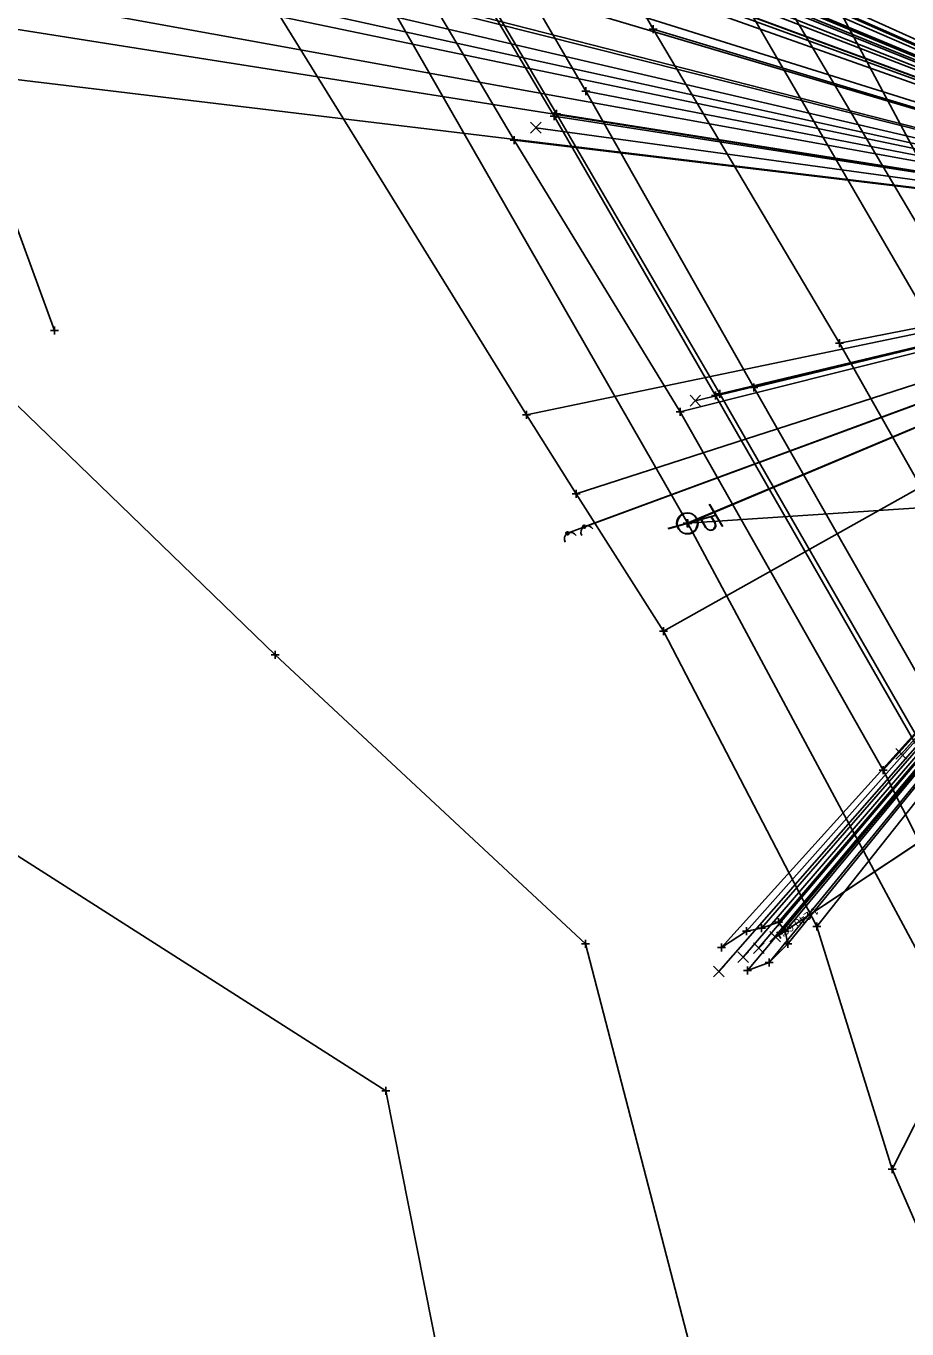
# Model space of a CAD drawing. Extents: x 125846 to 128609, y 511011 to 513388.
# Drawn here: x 126802 to 126912, y 512185.5 to 512348.3 of the extents above; entities that cross this region are included whole.
import ezdxf

# ---------------------------------------------------------------- set-up
doc = ezdxf.new("R2010")
doc.units = 0
for name, color, linetype in [('Default', 7, 'Continuous'), ('DR_X_Elev_Flow', 7, 'Continuous'), ('DR_X_Storm_Sewer', 7, 'Continuous'), ('DT_X_Terrain_Boundary', 7, 'Continuous'), ('PM_X_CL_Double_Solid', 7, 'Continuous'), ('PM_X_Edge_Line', 7, 'Continuous'), ('PV_X_COP', 7, 'Continuous'), ('PV_X_EOP', 7, 'Continuous'), ('PV_X_Shoulder_Aggregate', 7, 'Continuous'), ('SC_Scratch1', 7, 'Continuous'), ('SV_Observation', 7, 'Continuous'), ('SV_X_Break_Lines', 7, 'Continuous'), ('UT_X_Overhead_Cable_TV', 7, 'Continuous'), ('UT_X_Overhead_Electric', 7, 'Continuous'), ('UT_X_Overhead_Telecom', 7, 'Continuous'), ('UT_X_Sanitary_Line', 7, 'Continuous'), ('UT_X_Water', 7, 'Continuous')]:
    doc.layers.add(name, color=color, linetype=linetype)

msp = doc.modelspace()

# ---------------------------------------------------------------- linework, layer by layer
at = {"layer": 'Default'}
msp.add_lwpolyline([(126950.27, 512270.71), (126896.04, 512234.72)], dxfattribs=at)
at = {"layer": 'DR_X_Elev_Flow'}
for p, q in [((126895.78, 512235.15), (126896.29, 512234.29)), ((126896.47, 512234.98), (126895.61, 512234.46)), ((126896.04, 512234.72), (126896.04, 512234.72))]:
    msp.add_line(p, q, dxfattribs=at)
at = {"layer": 'DR_X_Storm_Sewer'}
msp.add_line((126950.27, 512270.71), (126896.04, 512234.72), dxfattribs=at)
at = {"layer": 'DT_X_Terrain_Boundary'}
for p, q in [((126888.13, 512287.21), (126882.16, 512285.53)), ((126888.21, 512287.19), (126882.24, 512285.5)), ((126888.95, 512285.84), (126887.32, 512288.59)), ((126889.03, 512285.81), (126887.4, 512288.56)), ((126886.27, 512286.69), (126886.87, 512285.66)), ((126886.35, 512286.66), (126886.96, 512285.63)), ((126887.54, 512287.04), (126887.97, 512286.31)), ((126887.62, 512287.02), (126888.05, 512286.29))]:
    msp.add_line(p, q, dxfattribs=at)
msp.add_lwpolyline([(125846.69, 513261.19), (125875.31, 513245.95), (126009.25, 513207.63), (126080.54, 513192), (126142.96, 513158.02), (126206.38, 513135.49), (126259.08, 513074.36), (126304.85, 512994.55), (126350.94, 512892.86), (126399.4, 512837.01), (126444.39, 512764.88), (126478.48, 512701.77), (126505.17, 512625.3), (126548.6, 512574.83), (126585.51, 512529.31), (126642.38, 512427.86), (126692.36, 512342.31), (126792.51, 512249.95), (126846.91, 512215.27), (126869.14, 512103.04), (126895.84, 512003)], dxfattribs=at)
for centre, radius in [((126884.55, 512286.2), 1.3), ((126884.63, 512286.17), 1.3), ((126871.68, 512285.77), 0.2), ((126869.6, 512284.94), 0.2)]:
    msp.add_circle(centre, radius, dxfattribs=at)
for centre, radius, start, end in [((126872.08, 512285.08), 0.8, 30.7503, 210.7503), ((126887.43, 512285.98), 0.638, 209.627, 31.8736), ((126887.51, 512285.95), 0.638, 209.627, 31.8736), ((126870.01, 512284.25), 0.8, 30.7503, 210.7503)]:
    msp.add_arc(centre, radius, start, end, dxfattribs=at)
at = {"layer": 'PM_X_CL_Double_Solid'}
msp.add_lwpolyline([(126939.36, 512245.71), (126926.53, 512268.2), (126903.61, 512308.72), (126880.31, 512347.95), (126860.08, 512383.78), (126836.45, 512422.71), (126813.37, 512462.31), (126785.22, 512508.84), (126764.44, 512544.16), (126739.79, 512584.78), (126713.11, 512629.69), (126694.8, 512659.53), (126673.4, 512694.56), (126659.78, 512718.87), (126636.02, 512759.4), (126615.05, 512794.2)], dxfattribs=at)
at = {"layer": 'PM_X_Edge_Line'}
for points in [[(126939.76, 512268.27), (126934.83, 512276.58), (126914.19, 512312.69), (126890.63, 512353.25), (126869.42, 512389.87), (126846.67, 512428.48), (126823.41, 512467.73), (126794.97, 512514.66), (126774.58, 512549.57), (126749.78, 512590.91), (126723.56, 512634.84), (126704.42, 512666.64), (126684.14, 512700.85), (126669.31, 512725.83), (126646.48, 512764.3), (126625.05, 512800.49)], [(127014.22, 511994.67), (127008.74, 512027.93), (127002.46, 512058.5), (126993.31, 512093.24), (126982.03, 512126.92), (126970.04, 512156.98), (126953.19, 512193.55), (126935.8, 512226.68), (126917.39, 512260.22), (126892.88, 512303.17), (126871.92, 512340.19), (126849.82, 512378.04), (126827.08, 512416.35), (126803.29, 512457.19), (126775.62, 512503), (126753.96, 512539.45), (126730.45, 512578.35), (126703.69, 512623.21), (126684.57, 512654.53), (126663.09, 512690.45), (126641.9, 512726.19), (126625.34, 512754.34)]]:
    msp.add_lwpolyline(points, dxfattribs=at)
at = {"layer": 'PV_X_COP'}
msp.add_lwpolyline([(127025.59, 511995.55), (127019.45, 512030.69), (127013.3, 512061.05), (127004.63, 512096.26), (126993.03, 512130.62), (126980.7, 512161.86), (126964.16, 512198.2), (126949.17, 512227.35), (126939.36, 512245.71), (126926.53, 512268.2), (126903.61, 512308.72), (126880.31, 512347.95), (126860.08, 512383.78), (126836.45, 512422.71), (126813.37, 512462.31), (126785.22, 512508.84), (126764.44, 512544.16), (126739.79, 512584.78), (126713.11, 512629.69), (126694.8, 512659.53), (126673.4, 512694.56), (126659.78, 512718.87), (126636.02, 512759.4), (126615.05, 512794.2)], dxfattribs=at)
at = {"layer": 'PV_X_EOP'}
for points in [[(127009.24, 511994.68), (127003.85, 512026.38), (126997.51, 512058.07), (126988.66, 512091.67), (126977.69, 512125.16), (126966.08, 512154.56), (126949.33, 512191.55), (126932.37, 512224.67), (126914.07, 512258.17), (126888.63, 512302.37), (126868.22, 512337.37), (126845.35, 512376.1), (126823.19, 512414), (126798.67, 512454.84), (126771.81, 512500.22), (126749.09, 512537.74), (126726.79, 512574.99), (126699.29, 512620.77), (126681.79, 512650.22), (126658.69, 512688.93), (126637.98, 512724.06), (126621.53, 512752.01)], [(127037.88, 512019.28), (127029.7, 512062.96), (127023.05, 512092.2), (127012.4, 512127.76), (127009.4, 512137.03), (126996.87, 512167.97), (126984.43, 512195.87), (126972.83, 512218.04), (126964.85, 512234.2), (126954.02, 512254.15), (126946.28, 512268.48), (126939.96, 512279.02), (126918.51, 512314.81), (126894.74, 512355.01), (126873.07, 512391.8), (126850.03, 512430.62), (126826.94, 512469.56), (126798.53, 512517.08)]]:
    msp.add_lwpolyline(points, dxfattribs=at)
at = {"layer": 'PV_X_Shoulder_Aggregate'}
for points in [[(126958.84, 512266.38), (126954.95, 512268.11), (126951.37, 512267.01), (126950.82, 512267.63), (126947.71, 512272.62), (126942.59, 512279.94), (126923.26, 512313.49), (126899.24, 512358.52), (126887.06, 512383.39), (126879.44, 512396.24), (126854.35, 512434.48), (126831.72, 512472.74), (126803.3, 512520.89), (126783.27, 512554.62), (126752.52, 512603.43), (126737.93, 512626.87), (126732.3, 512635.67), (126721.04, 512651.9), (126710.1, 512670.46), (126691.09, 512704.83), (126677.85, 512725.45), (126654.7, 512768.66), (126631.69, 512807.54)], [(127001.96, 511993.51), (126995.22, 512024.86), (126988.72, 512057.22), (126979.9, 512089.29), (126975.16, 512101.99), (126973.89, 512105.14), (126967.21, 512120.99), (126955.55, 512150.69), (126941.55, 512187.26), (126925.87, 512221.96), (126909.07, 512255.35), (126883.68, 512300.11), (126862.94, 512334.06), (126844.36, 512365.44), (126840.97, 512368.63), (126839.14, 512371.49), (126839.18, 512375.17), (126816.49, 512410.45), (126794.03, 512452.96), (126773.19, 512490.81), (126746.65, 512537.28)]]:
    msp.add_lwpolyline(points, dxfattribs=at)
at = {"layer": 'SV_Observation'}
for p in [(126786.23, 512400.45), (126727.19, 512397.15), (126814.49, 512385.66), (126821.17, 512376.04), (126839.18, 512375.17), (126844.97, 512375.96), (126845.35, 512376.1), (126841.19, 512374.83), (126842.48, 512372.4), (126839.14, 512371.49), (126843.76, 512370.56), (126840.97, 512368.63), (126844.36, 512365.44), (126846.94, 512365.74), (126848.4, 512357.16), (126808.82, 512354.73), (126824.97, 512354.9), (126836, 512354.88), (126837.31, 512355.05), (126894.74, 512355.01), (126790.68, 512353.63), (126890.63, 512353.25), (126774.58, 512352.09), (126832.62, 512351.28), (126738.1, 512349.2), (126880.31, 512347.95), (126880.31, 512347.95), (126871.92, 512340.19), (126867.94, 512337.07), (126868.22, 512337.37), (126865.67, 512335.64), (126862.94, 512334.06), (126864.5, 512299.73), (126869.6, 512284.94), (126870.71, 512289.89), (126871.68, 512285.77), (126881.61, 512272.71), (126883.68, 512300.11), (126884.55, 512286.2), (126884.55, 512286.2), (126884.55, 512286.2), (126884.55, 512286.2), (126884.63, 512286.17), (126884.63, 512286.17), (126884.63, 512286.17), (126884.63, 512286.17), (126885.58, 512301.52), (126888.12, 512302.18), (126888.53, 512230.17), (126888.63, 512302.37), (126888.85, 512233.17), (126891.56, 512231.95), (126891.96, 512235.2), (126892.09, 512230.28), (126892.88, 512303.17), (126893.5, 512233.1), (126893.86, 512235.58), (126894.82, 512231.3), (126895.56, 512234.53), (126895.99, 512236.32), (126896.04, 512234.72), (126896.8, 512235.22), (126897.13, 512233.65), (126900.78, 512235.79), (126903.61, 512308.72), (126903.61, 512308.72), (126909.07, 512255.35), (126910.2, 512205.45), (126911.33, 512257.38)]:
    msp.add_line(p, (126968.53, 512321.46), dxfattribs=at)
at = {"layer": 'SV_X_Break_Lines'}
for points in [[(126929.12, 511999.3), (126903.84, 512110.39), (126871.86, 512233.61), (126833.09, 512269.75), (126730.01, 512369.5), (126679.2, 512443.95), (126610.71, 512557), (126575.33, 512586.13), (126534.96, 512653.66), (126509.99, 512711.61), (126473.57, 512790.72), (126439.57, 512852.97), (126379.8, 512929.28), (126333.79, 513016.36), (126275.48, 513095.64), (126210.09, 513171.16), (126150.48, 513199.56), (126106, 513214.69), (126034.78, 513236.32), (125916.78, 513276.5), (125860.26, 513285.89)], [(126895.84, 512003), (126869.14, 512103.04), (126846.91, 512215.27), (126792.51, 512249.95), (126692.36, 512342.31), (126642.38, 512427.86), (126585.51, 512529.31), (126548.6, 512574.83), (126505.17, 512625.3), (126478.48, 512701.77), (126444.39, 512764.88), (126399.4, 512837.01), (126350.94, 512892.86), (126304.85, 512994.55), (126259.08, 513074.36), (126206.38, 513135.49), (126142.96, 513158.02), (126080.54, 513192), (126009.25, 513207.63), (125875.31, 513245.95), (125846.69, 513261.19)], [(126999.24, 512048.23), (126997.06, 512058.07), (126988.34, 512091.59), (126977.21, 512124.94), (126965.68, 512154.42), (126948.87, 512191.35), (126932.05, 512224.53), (126913.55, 512257.84), (126888.12, 512302.18), (126867.94, 512337.07), (126844.97, 512375.96), (126822.58, 512413.6), (126798.13, 512454.65), (126771.42, 512499.97), (126748.75, 512537.41)], [(126989.09, 511993.49), (126980.94, 512025.86), (126967.03, 512063.12), (126962.78, 512075.93), (126957.39, 512096.52), (126946.61, 512119.08), (126939.72, 512136.21), (126938.97, 512147.49), (126920.77, 512181.18), (126910.2, 512205.45), (126900.78, 512235.79), (126881.61, 512272.71), (126870.71, 512289.89), (126864.5, 512299.73), (126832.62, 512351.28), (126821.17, 512376.04), (126814.49, 512385.66), (126793.51, 512427.95), (126772.9, 512464.25), (126745.26, 512500.91), (126725.82, 512527.86)], [(126805.51, 512310.3), (126794.91, 512339.16), (126786.75, 512361.5), (126775.2, 512380.84), (126759, 512398.08), (126742.91, 512417.36), (126727.9, 512436.02), (126707.37, 512459.12), (126686.31, 512477.71), (126675.79, 512483.7)], [(126892.09, 512230.28), (126894.82, 512231.3), (126897.13, 512233.65), (126896.8, 512235.22), (126895.99, 512236.32), (126893.86, 512235.58), (126891.96, 512235.2), (126888.85, 512233.17)]]:
    msp.add_lwpolyline(points, dxfattribs=at)
at = {"layer": 'UT_X_Overhead_Cable_TV'}
for points in [[(127118.02, 511376.72), (127063.55, 511579.79), (127023.04, 511824.95), (126985.21, 512054.96), (126933.25, 512195.56), (126884.63, 512286.17), (126796.71, 512439.39), (126673.51, 512645.42), (126573.76, 512808.4), (126463.86, 512978.44), (126309.69, 513169.01), (126131.86, 513264.58), (125938.03, 513331.21)], [(127377.69, 512315.67), (127160.8, 512301.41), (126951.89, 512290.68), (126884.55, 512286.2)]]:
    msp.add_lwpolyline(points, dxfattribs=at)
at = {"layer": 'UT_X_Overhead_Electric'}
for points in [[(127118.02, 511376.72), (127063.55, 511579.79), (127023.04, 511824.95), (126985.21, 512054.96), (126933.25, 512195.56), (126884.63, 512286.17), (126796.71, 512439.39), (126673.51, 512645.42), (126573.76, 512808.4), (126463.86, 512978.44), (126309.69, 513169.01), (126131.86, 513264.58), (125938.03, 513331.21)], [(127377.69, 512315.67), (127160.8, 512301.41), (126951.89, 512290.68), (126884.55, 512286.2)]]:
    msp.add_lwpolyline(points, dxfattribs=at)
at = {"layer": 'UT_X_Overhead_Telecom'}
for points in [[(126933.25, 512195.56), (126884.63, 512286.17), (126796.71, 512439.39), (126673.51, 512645.42)], [(127377.69, 512315.67), (127160.8, 512301.41), (126951.89, 512290.68), (126884.55, 512286.2)]]:
    msp.add_lwpolyline(points, dxfattribs=at)
at = {"layer": 'UT_X_Sanitary_Line'}
for p, q in [((126879.81, 512347.95), (126880.81, 512347.95)), ((126879.81, 512347.95), (126880.81, 512347.95)), ((126880.31, 512348.45), (126880.31, 512347.45)), ((126880.31, 512348.45), (126880.31, 512347.45)), ((126880.31, 512347.95), (126880.31, 512347.95)), ((126880.31, 512347.95), (126880.31, 512347.95)), ((126871.42, 512340.19), (126872.42, 512340.19)), ((126871.92, 512340.69), (126871.92, 512339.69)), ((126871.92, 512340.19), (126871.92, 512340.19)), ((126868.22, 512337.87), (126868.22, 512336.87)), ((126867.44, 512337.07), (126868.44, 512337.07)), ((126867.72, 512337.37), (126868.72, 512337.37)), ((126867.94, 512337.57), (126867.94, 512336.57)), ((126867.94, 512337.07), (126867.94, 512337.07)), ((126868.22, 512337.37), (126868.22, 512337.37)), ((126862.94, 512334.56), (126862.94, 512333.56)), ((126862.44, 512334.06), (126863.44, 512334.06)), ((126862.94, 512334.06), (126862.94, 512334.06)), ((126805.01, 512310.3), (126806.01, 512310.3)), ((126805.51, 512310.8), (126805.51, 512309.8)), ((126805.51, 512310.3), (126805.51, 512310.3)), ((126903.11, 512308.72), (126904.11, 512308.72)), ((126903.11, 512308.72), (126904.11, 512308.72)), ((126903.61, 512309.22), (126903.61, 512308.22)), ((126903.61, 512309.22), (126903.61, 512308.22)), ((126903.61, 512308.72), (126903.61, 512308.72)), ((126903.61, 512308.72), (126903.61, 512308.72)), ((126892.88, 512303.67), (126892.88, 512302.67)), ((126887.62, 512302.18), (126888.62, 512302.18)), ((126888.12, 512302.68), (126888.12, 512301.68)), ((126888.12, 512302.18), (126888.12, 512302.18)), ((126888.13, 512302.37), (126889.13, 512302.37)), ((126888.63, 512302.87), (126888.63, 512301.87)), ((126888.63, 512302.37), (126888.63, 512302.37)), ((126892.38, 512303.17), (126893.38, 512303.17)), ((126892.88, 512303.17), (126892.88, 512303.17)), ((126864.5, 512300.23), (126864.5, 512299.23)), ((126883.68, 512300.61), (126883.68, 512299.61)), ((126864, 512299.73), (126865, 512299.73)), ((126864.5, 512299.73), (126864.5, 512299.73)), ((126883.18, 512300.11), (126884.18, 512300.11)), ((126883.68, 512300.11), (126883.68, 512300.11)), ((126870.71, 512290.39), (126870.71, 512289.39)), ((126870.21, 512289.89), (126871.21, 512289.89)), ((126870.71, 512289.89), (126870.71, 512289.89)), ((126884.05, 512286.2), (126885.05, 512286.2)), ((126884.05, 512286.2), (126885.05, 512286.2)), ((126884.05, 512286.2), (126885.05, 512286.2)), ((126884.13, 512286.17), (126885.13, 512286.17)), ((126884.13, 512286.17), (126885.13, 512286.17)), ((126884.13, 512286.17), (126885.13, 512286.17)), ((126884.55, 512286.7), (126884.55, 512285.7)), ((126884.55, 512286.7), (126884.55, 512285.7)), ((126884.55, 512286.7), (126884.55, 512285.7)), ((126884.55, 512286.2), (126884.55, 512286.2)), ((126884.55, 512286.2), (126884.55, 512286.2)), ((126884.55, 512286.2), (126884.55, 512286.2)), ((126884.63, 512286.67), (126884.63, 512285.67)), ((126884.63, 512286.67), (126884.63, 512285.67)), ((126884.63, 512286.67), (126884.63, 512285.67)), ((126884.63, 512286.17), (126884.63, 512286.17)), ((126884.63, 512286.17), (126884.63, 512286.17)), ((126884.63, 512286.17), (126884.63, 512286.17)), ((126881.11, 512272.71), (126882.11, 512272.71)), ((126881.61, 512273.21), (126881.61, 512272.21)), ((126881.61, 512272.71), (126881.61, 512272.71)), ((126832.59, 512269.75), (126833.59, 512269.75)), ((126833.09, 512270.25), (126833.09, 512269.25)), ((126833.09, 512269.75), (126833.09, 512269.75)), ((126908.57, 512255.35), (126909.57, 512255.35)), ((126909.07, 512255.85), (126909.07, 512254.85)), ((126909.07, 512255.35), (126909.07, 512255.35)), ((126895.99, 512236.82), (126895.99, 512235.82)), ((126891.46, 512235.2), (126892.46, 512235.2)), ((126891.96, 512235.7), (126891.96, 512234.7)), ((126891.96, 512235.2), (126891.96, 512235.2)), ((126893.36, 512235.58), (126894.36, 512235.58)), ((126893.86, 512236.08), (126893.86, 512235.08)), ((126893.86, 512235.58), (126893.86, 512235.58)), ((126895.49, 512236.32), (126896.49, 512236.32)), ((126895.99, 512236.32), (126895.99, 512236.32)), ((126896.3, 512235.22), (126897.3, 512235.22)), ((126896.8, 512235.72), (126896.8, 512234.72)), ((126896.8, 512235.22), (126896.8, 512235.22)), ((126900.28, 512235.79), (126901.28, 512235.79)), ((126900.78, 512236.29), (126900.78, 512235.29)), ((126900.78, 512235.79), (126900.78, 512235.79)), ((126871.36, 512233.61), (126872.36, 512233.61)), ((126871.86, 512234.11), (126871.86, 512233.11)), ((126871.86, 512233.61), (126871.86, 512233.61)), ((126888.85, 512233.67), (126888.85, 512232.67)), ((126896.63, 512233.65), (126897.63, 512233.65)), ((126897.13, 512234.15), (126897.13, 512233.15)), ((126897.13, 512233.65), (126897.13, 512233.65)), ((126888.35, 512233.17), (126889.35, 512233.17)), ((126888.85, 512233.17), (126888.85, 512233.17)), ((126894.82, 512231.8), (126894.82, 512230.8)), ((126891.59, 512230.28), (126892.59, 512230.28)), ((126892.09, 512230.78), (126892.09, 512229.78)), ((126892.09, 512230.28), (126892.09, 512230.28)), ((126894.32, 512231.3), (126895.32, 512231.3)), ((126894.82, 512231.3), (126894.82, 512231.3)), ((126846.91, 512215.77), (126846.91, 512214.77)), ((126846.41, 512215.27), (126847.41, 512215.27)), ((126846.91, 512215.27), (126846.91, 512215.27)), ((126910.2, 512205.95), (126910.2, 512204.95)), ((126909.7, 512205.45), (126910.7, 512205.45)), ((126910.2, 512205.45), (126910.2, 512205.45))]:
    msp.add_line(p, q, dxfattribs=at)
at = {"layer": 'UT_X_Water'}
for p, q in [((126865, 512334.97), (126866.34, 512336.31)), ((126865, 512336.31), (126866.34, 512334.97)), ((126884.92, 512300.85), (126886.25, 512302.19)), ((126884.92, 512302.19), (126886.25, 512300.85)), ((126910.66, 512256.71), (126911.99, 512258.05)), ((126910.66, 512258.05), (126911.99, 512256.71)), ((126894.89, 512233.86), (126896.22, 512235.19)), ((126894.89, 512235.19), (126896.22, 512233.86)), ((126892.84, 512232.43), (126894.17, 512233.77)), ((126892.84, 512233.77), (126894.17, 512232.43)), ((126890.9, 512231.29), (126892.23, 512232.62)), ((126890.9, 512232.62), (126892.23, 512231.29)), ((126887.87, 512229.5), (126889.2, 512230.84)), ((126887.87, 512230.84), (126889.2, 512229.5))]:
    msp.add_line(p, q, dxfattribs=at)

# ---------------------------------------------------------------- texts
at = {"layer": 'SC_Scratch1'}
msp.add_text("1,240.63'", height=1, rotation=213.574, dxfattribs=at).set_placement((126900.58, 512238.33))

doc.saveas('drawing.dxf')
